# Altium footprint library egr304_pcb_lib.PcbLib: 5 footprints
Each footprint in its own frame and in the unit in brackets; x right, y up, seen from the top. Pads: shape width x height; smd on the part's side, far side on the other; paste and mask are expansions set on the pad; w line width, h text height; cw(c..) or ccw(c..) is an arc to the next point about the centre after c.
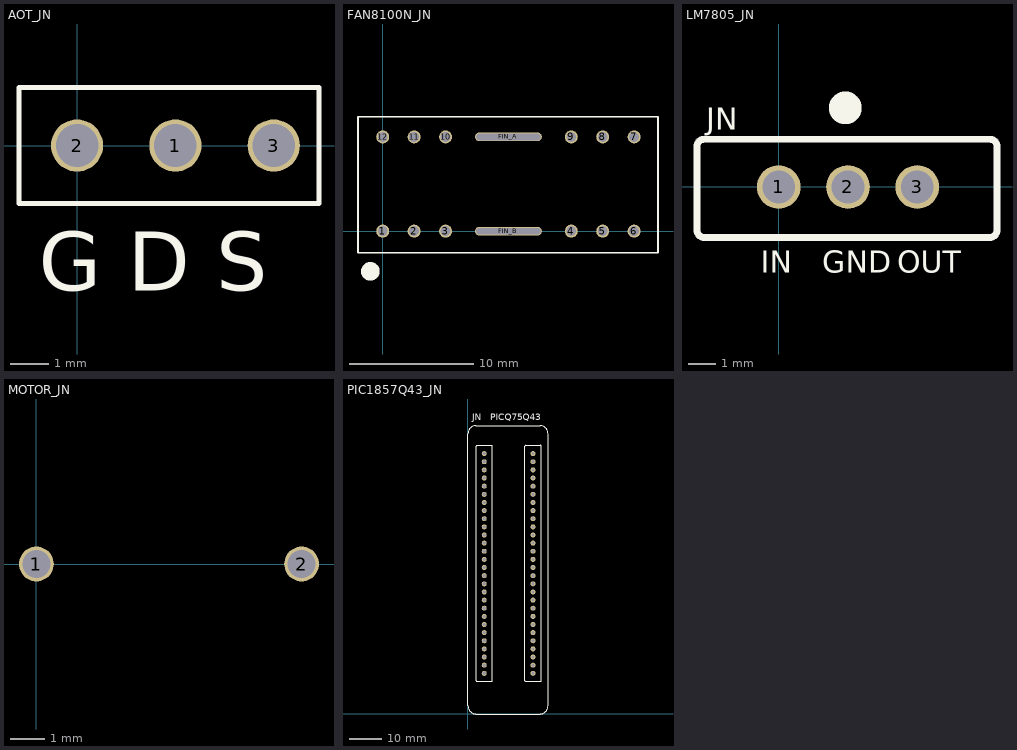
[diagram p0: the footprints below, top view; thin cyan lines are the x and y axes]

## AOT_JN [mm]
pads (3):
  round 1.35 hole 1.1 paste-2539.97 mask+0.1: 1(2.54,0) 2(0,0)
  round 1.35 hole 1.1 paste-2539.97 mask-2539.97: 3(5.08,0)
Top Overlay:
  lines w0.127: -1.5,-1.5 6.25,-1.5 6.25,1.5 -1.5,1.5 -1.5,-1.5
  text "G D S" at -0.996,-3.746 h1.52
Top Solder:
  circle w0.775: c5.08,0 r0.387
Bottom Solder:
  circle w0: c5.08,0 r0

## FAN8100N_JN [mm]
pads (14):
  round 1.05 hole 0.8 paste-2539.97 mask+0.1: 1(0,0) 2(2.54,0) 3(5.08,0) 4(15.24,0) 5(17.78,0) 6(20.32,0) 7(20.32,7.62) 8(17.78,7.62) 9(15.24,7.62) 10(5.08,7.62) 11(2.54,7.62) 12(0,7.62)
  oval 5.4x0.7 hole 0.5 slot 5.2 at 0 deg paste-2539.97 mask+0.1: FIN_A(10.16,7.62) FIN_B(10.16,0)
Top Overlay:
  circle w1: c-1,-3.25 r0.25
  lines w0.127: -2,-1.75 -2,9.25 22.25,9.25 22.25,-1.75 -1.875,-1.75 -2,-1.75

## LM7805_JN [mm]
pads (3):
  round 1.6 hole 1.2 paste-2539.97 mask+0.1: 1(0,0) 2(2.54,0) 3(5.08,0)
Top Overlay:
  circle w1: c2.44,2.9 r0.1
  lines w0.254: -2.996,-1.596 ccw(c-2.742,-1.596) -2.742,-1.85 7.75,-1.85 ccw(c7.75,-1.596) 8.004,-1.596 8.004,1.496 ccw(c7.75,1.496) 7.75,1.75 -2.742,1.75 ccw(c-2.742,1.496) -2.996,1.496 -2.996,-1.596
  text "JN" at -2.65,2.1 h0.8
  text "OUT" at 4.35,-3.15 h0.8
  text "GND" at 1.6,-3.15 h0.8
  text "IN" at -0.65,-3.15 h0.8

## MOTOR_JN [mm]
pads (2):
  round 1 hole 0.8 paste-2539.97 mask+0.1: 1(0,0) 2(7.62,0)

## PIC1857Q43_JN [mm]
pads (56):
  round 1.55 hole 1 paste-2539.97 mask+0.1: 1(5.08,81.28) 2(5.08,78.74) 3(5.08,76.2) 4(5.08,73.66) 5(5.08,71.12) 6(5.08,68.58) 7(5.08,66.04) 8(5.08,63.5) 9(5.08,60.96) 10(5.08,58.42) 11(5.08,55.88) 12(5.08,53.34) 13(5.08,50.8) 14(5.08,48.26) 15(5.08,45.72) 16(5.08,43.18) 17(5.08,40.64) 18(5.08,38.1) 19(5.08,35.56) 20(5.08,33.02) 21(5.08,30.48) 22(5.08,27.94) 23(5.08,25.4) 24(5.08,22.86) 25(5.08,20.32) 26(5.08,17.78) 27(5.08,15.24) 28(5.08,12.7) 29(20.32,81.28) 30(20.32,78.74) 31(20.32,76.2) 32(20.32,73.66) 33(20.32,71.12) 34(20.32,68.58) 35(20.32,66.04) 36(20.32,63.5) 37(20.32,60.96) 38(20.32,58.42) 39(20.32,55.88) 40(20.32,53.34) 41(20.32,50.8) 42(20.32,48.26) 43(20.32,45.72) 44(20.32,43.18) 45(20.32,40.64) 46(20.32,38.1) 47(20.32,35.56) 48(20.32,33.02) 49(20.32,30.48) 50(20.32,27.94) 51(20.32,25.4) 52(20.32,22.86) 53(20.32,20.32) 54(20.32,17.78) 55(20.32,15.24) 56(20.32,12.7)
Top Overlay:
  lines w0.254: 0,2.5 ccw(c2.5,2.5) 2.5,0 22.5,0 ccw(c22.5,2.5) 25,2.5 25,87.5 ccw(c22.5,87.5) 22.5,90 2.5,90 ccw(c2.5,87.5) 0,87.5 0,2.5 ; 2.54,10.414 ccw(c2.794,10.414) 2.794,10.16 7.366,10.16 ccw(c7.366,10.414) 7.62,10.414 7.62,83.566 ccw(c7.366,83.566) 7.366,83.82 2.794,83.82 ccw(c2.794,83.566) 2.54,83.566 2.54,10.414 ; 17.78,10.414 ccw(c18.034,10.414) 18.034,10.16 22.606,10.16 ccw(c22.606,10.414) 22.86,10.414 22.86,83.566 ccw(c22.606,83.566) 22.606,83.82 18.034,83.82 ccw(c18.034,83.566) 17.78,83.566 17.78,10.414
  text "JN" at 1.4,91.65 h2
  text "PICQ75Q43" at 6.9,91.65 h2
